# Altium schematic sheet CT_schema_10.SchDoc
size 278 x 170 mm
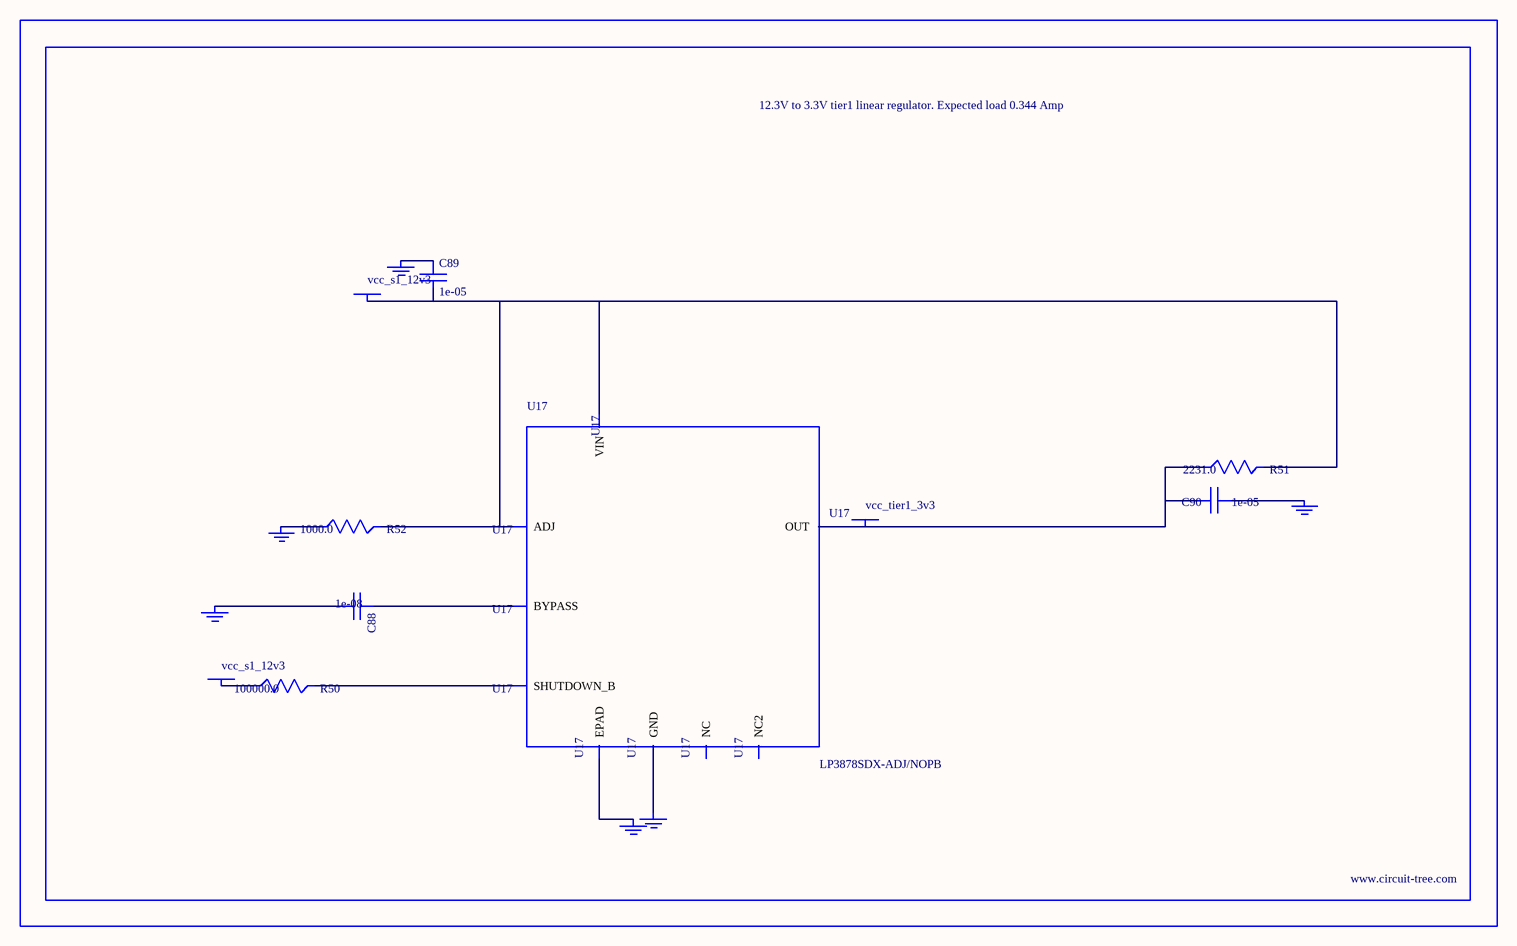
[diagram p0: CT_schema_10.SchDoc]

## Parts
BORDER9  (no value)
C88  1e-08  [C0402]
C89  1e-05  [C1210]
C90  1e-05  [C1210]
GND_INSTANCE_9_0  (no value)
GND_INSTANCE_9_1  (no value)
GND_INSTANCE_9_2  (no value)
GND_INSTANCE_9_3  (no value)
GND_INSTANCE_9_4  (no value)
GND_INSTANCE_9_5  (no value)
POWER_INSTANCE_9_0  vcc_s1_12v3
POWER_INSTANCE_9_1  vcc_s1_12v3
POWER_INSTANCE_9_2  vcc_tier1_3v3
R50  100000.0  [R0603]
R51  2231.0  [R0603]
R52  1000.0  [R0603]
U17  LP3878SDX-ADJ/NOPB  [WSON-8]

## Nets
NetC88_1: C88.1 U17.1(BYPASS)
NetC88_2: C88.2 GND_INSTANCE_9_0.0(GND)
NetC89_1: C89.1 GND_INSTANCE_9_1.0(GND)
NetC89_2: C89.2 POWER_INSTANCE_9_0.0(PWR) R51.2 R52.2 U17.4(VIN) U17.6(ADJ)
NetC90_1: C90.1 GND_INSTANCE_9_2.0(GND)
NetC90_2: C90.2 POWER_INSTANCE_9_2.0(PWR) R51.1 U17.5(OUT)
NetGND_INSTANCE_9_3_0: GND_INSTANCE_9_3.0(GND) R52.1
NetGND_INSTANCE_9_4_0: GND_INSTANCE_9_4.0(GND) U17.PAD(EPAD)
NetGND_INSTANCE_9_5_0: GND_INSTANCE_9_5.0(GND) U17.3(GND)
NetPOWER_INSTANCE_9_1_0: POWER_INSTANCE_9_1.0(PWR) R50.1
NetR50_2: R50.2 U17.8(SHUTDOWN_B)

Not connected (* = marked no-connect by the designer): U17 2(NC) 7(NC2)

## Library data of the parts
BORDER9 = BORDER_PAGE9
C88 = C0402C103K3RAC
C89 = C1210C106K5PACTU
C90 = GRM32DR61E106MA12L
GND_INSTANCE_9_0-GND_INSTANCE_9_5 = GND
POWER_INSTANCE_9_0-POWER_INSTANCE_9_2 = PWR
R50 = RC0603JR-07100KL
R51 = R51
R52 = RC0603JR-071KL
